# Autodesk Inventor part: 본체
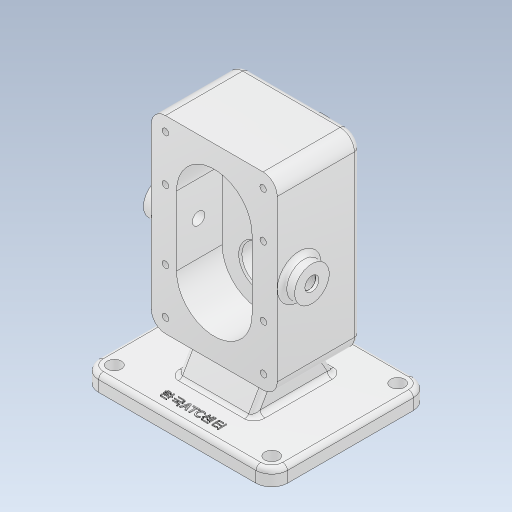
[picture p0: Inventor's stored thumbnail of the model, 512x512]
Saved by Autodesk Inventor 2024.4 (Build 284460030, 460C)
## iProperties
Created: 2026-10
Part Number: 본체
Material: 알루미늄 6061
Document SubType Name: Modeling
Designer: user
Density: 2.7 g/cm^3
Appearance: 알루미늄 - 평지
Mass: 1471.32 g
Surface Area: 816.506 cm^2
Volume: 544.934 cm^3
Author: user
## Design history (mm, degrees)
sketch "스케치1"
  geometry: 1 further point
sketch "스케치2"
  geometry: L1 (-40, 60)-(40, 60); L2 (40, 60)-(40, -60); L3 (40, -60)-(-40, -60); L4 (-40, -60)-(-40, 60); L5 (-40, 60)-(40, -60); L6 (40, 60)-(-40, -60); L7 (-60, -80)-(60, -80); L8 (60, -80)-(60, -90); L9 (60, -90)-(-60, -90); L10 (-60, -90)-(-60, -80); 4 further points
  constraints: 20 end point, 5 midpoint, 4 parallel, 2 horizontal, 2 perpendicular, 1 vertical alignment
  dimensions: "d0" = 80 distance of L2.end L3.end; "d1" = 120 distance between parallel lines of L1 L3; "d2" = 10 distance between parallel lines of L7 L9; "d3" = 120 distance of point (60, -85) point (-60, -85); "d4" = 90 distance from line of point (0, 0) L9
extrude "돌출1" new body sketch "스케치2" stored distance "d5" = 53; taper "d6" = 0 deg
extrude "돌출2" join sketch "스케치2" stored distance "d7" = 100; taper "d8" = 0 deg
sketch "스케치4"
  geometry: L1 (-60, 26.5)-(-60, -26.5) reference; L2 (-60, 14.953)-(-80, 26.5); L3 (-80, -50)-(-80, 50) reference; L4 (-60, -14.953)-(-80, -26.5); L5 (-60, 14.953)-(-60, -14.953); L6 (-80, 26.5)-(-80, -26.5); 4 further points
  constraints: 8 end point, 2 point on line, 1 collinear, 1 equal length, 1 horizontal alignment, 1 midpoint, 1 vertical
  dimensions: "d11" = 53 distance of L4.end L2.end; "d12" = 60 deg angle of L3 L2
extrude "돌출3" join sketch "스케치4" stored distance "d13" = 48; taper "d14" = 0 deg
sketch "스케치6"
  geometry: L1 (0, 22)-(0, -22); L2 (-24, 22)-(-24, -22); L3 (24, -22)-(24, 22); A1 r 24 centre (0, 22) between (24, 22) and (-24, 22); A2 r 24 centre (0, -22) between (-24, -22) and (24, -22); 2 further points
  constraints: 8 end point, 4 point on circle, 4 tangent, 2 centre point, 1 coincident, 1 midpoint, 1 parallel, 1 vertical
  dimensions: "d20" = 48 distance between parallel lines of L3 L2; "d21" = 44 distance of L1.start L1.end
extrude "돌출5" cut sketch "스케치6" distance "d22" = 29; taper "d23" = 0 deg
sketch "스케치7"
  geometry: L1 (53, 120)-(53, 0) reference; L2 (76.5, -30)-(-23.5, -30) reference; C1 r 11 at (39, 60); 1 further point
  constraints: 1 centre point
  dimensions: "d24" = 22 diameter of C1; "d25" = 90 distance from line of C1.centre L2; "d26" = 14 distance from line of L1 C1.centre
extrude "돌출6" join sketch "스케치7" distance "d27" = 8; taper "d28" = 0 deg
sketch "스케치9"
  geometry: C1 r 11 at (0, 0) reference; 2 further points
  constraints: 1 coincident
hole "구멍1" sketch "스케치9" at (0, 0) diameter "d29" = 7.9502; stored, may be unused: countersink angle "d35" = 90 deg, drill point angle "d37" = 118 deg; dims "d30" = 5.98424, "d31" = 0.62479, "d32" = 8.3632, "d33" = 9, "d34" = 2, "d36" = 8
sketch "스케치10"
  geometry: C1 r 19 at (0, 22); 1 further point
  constraints: 1 centre point, 1 vertical alignment
  dimensions: "d38" = 38 diameter of C1; "d39" = 22 distance of C1.centre point (0, 0)
extrude "돌출7" join sketch "스케치10" distance "d40" = 17; taper "d41" = 0 deg
sketch "스케치11"
  geometry: L1 (41, 43.5)-(3, 43.5) reference; L2 (-22, 2.5)-(22, 2.5) reference; L3 (22, 43.5)-(22, 2.5); L4 (46, 2.5)-(22, 2.5) reference; L5 (34.5, 2.5)-(34.5, 17.5); L6 (34.5, 17.5)-(30.5, 17.5); L7 (30.5, 17.5)-(30.5, 36.2); L8 (30.5, 36.2)-(35.5, 36.2); L9 (36, 36.7)-(36, 43.5); L10 (34.5, 2.5)-(22, 2.5); L11 (36, 43.5)-(30.5, 43.5); L12 (22, 43.5)-(36, 43.5); L13 (22, 2.5)-(22, 4.93); L14 (22, 2.5)-(22, 43.5); A1 r 0.5 centre (35.5, 36.7) between (35.5, 36.2) and (36, 36.7); 6 further points
  constraints: 22 end point, 5 midpoint, 5 perpendicular, 4 point on line, 2 collinear, 2 point on circle, 2 tangent, 1 centre point, 1 vertical
  dimensions: "d42" = 17 diameter of point (30.5, 26.85) L3; "d43" = 28 diameter of point (36, 40.1) L3; "d44" = 25 diameter of L5 L3; "d45" = 15 distance from line of point (32.5, 17.5) L4; "d46" = 7.3 distance from line of L1 point (33, 36.2); "d47" = 0.5 radius of A1
revolve "회전1" sketch "스케치11" stored, may be unused: angle "d48" = 90 deg
sketch "스케치13"
  geometry: C1 r 12.5 at (0, -22); A1 r 24 centre (0, -22) between (-24, -22) and (24, -22) reference; 1 further point
  constraints: 1 centre point, 1 coincident
  dimensions: "d50" = 25 diameter of C1
extrude "돌출8" cut sketch "스케치13" distance "d51" = 15; taper "d52" = 0 deg
sketch "스케치14"
  geometry: L1 (24, 22)-(24, -22) reference; L2 (-24, -22)-(-24, 22) reference; L3 (-40, -60)-(40, -60) reference; L4 (40, -60)-(40, 60) reference; L5 (40, 60)-(-40, 60) reference; L6 (-40, 60)-(-40, -60) reference; A1 r 24 centre (0, -22) between (-24, -22) and (24, -22) reference; A2 r 24 centre (0, 22) between (24, 22) and (-24, 22) reference; 1 further point
sketch "스케치15"
  geometry: L1 (-40, -60)-(40, -60) reference; L2 (40, 60)-(-40, 60) reference; L3 (-40, 60)-(-40, -60) reference; 9 further points
  constraints: 4 horizontal alignment, 3 vertical alignment
  dimensions: "d53" = 62 distance of point (31, 51) point (-31, 51); "d54" = 29 distance of point (31.096, 22) point (31, 51); "d55" = 29 distance of point (31.274, -51) point (31.24, -22); "d56" = 44 distance of point (31.096, 22) point (31.24, -22); "d57" = 9 distance from line of point (-31, 51) L3; "d58" = 9 distance from line of L2 point (31, 51); "d59" = 9.00041 distance from line of point (31.274, -51) L1; "d60" = 28.99998 distance of point (-31, -22) point (-31, -51); "d61" = 43.99976 distance of point (-31, 22) point (-31, -22)
hole "구멍2" sketch "스케치15" at (-31, 51), (31, 51), (31.096, 22), (-31, 22), (-31, -22), (31.24, -22), (31.274, -51), (-31, -51) diameter "d62" = 4.134; stored, may be unused: countersink angle "d66" = 90 deg, drill point angle "d68" = 118 deg; dims "d63" = 10, "d64" = 4, "d65" = 2, "d67" = 12
sketch "스케치16"
  geometry: L1 (36, 23.5)-(36, 76.5) reference; L2 (36, 76.5)-(84, 76.5) reference; L3 (84, 76.5)-(84, 23.5) reference; L4 (84, 23.5)-(36, 23.5) reference; L5 (0, 100)-(0, 0) reference; L6 (120, 0)-(0, 0) reference; L7 (120, 100)-(120, 0) reference; L8 (0, 100)-(120, 100) reference; 1 further point
sketch "스케치17"
  geometry: L1 (0, 100)-(120, 100) reference; 2 further points
  constraints: 1 vertical alignment, 1 other
  dimensions: "d69" = 10 distance from line of point (60, 90) L1
feature "엠보싱1" sketch "스케치17" dims "d0" = 80, "d1" = 120, "d11" = 53, "d12" = 60 deg, "d70" = 0.5, "d71" = 0
fillet "모깎기1" dims "d72" = 10
sketch "스케치18"
  geometry: C1 r 4.5 at (100, -90); C2 r 4.5 at (0, -90); C3 r 4.5 at (0, -10); C4 r 4.5 at (100, -10); A1 r 10 centre (100, -90) between (100, -100) and (110, -90) reference; A2 r 10 centre (100, -10) between (110, -10) and (100, 0) reference; A3 r 10 centre (0, -10) between (0, 0) and (-10, -10) reference; A4 r 10 centre (0, -90) between (-10, -90) and (0, -100) reference; 1 further point
  constraints: 4 centre point, 4 coincident
  dimensions: "d73" = 9 diameter of C1; "d74" = 9 diameter of C2; "d75" = 9 diameter of C3; "d76" = 9 diameter of C4
extrude "돌출9" cut sketch "스케치18" extent not by distance; stored distance "d77" = 15; taper "d78" = 0 deg
chamfer "모따기1" distance "d79" = 1; stored, may be unused: second distance "d80" = 2, angle "d81" = 45 deg
chamfer "모따기2" distance "d82" = 0.7; stored, may be unused: second distance "d83" = 2, angle "d84" = 30 deg
fillet "모깎기2" dims "d85" = 3
fillet "모깎기3" dims "d86" = 3
fillet "모깎기4" dims "d87" = 3
fillet "모깎기5" dims "d88" = 3
fillet "모깎기6" dims "d89" = 9
fillet "모깎기7" dims "d90" = 4
node "솔리드1"
mirror "미러1"
feature "A9D066F2-1C7D-4E18-AEED-F7BC21143FA4" dims "d62" = 4.134, "d63" = 10, "d64" = 4, "d65" = 2, "d66" = 90 deg, "d67" = 12, "d68" = 118 deg
